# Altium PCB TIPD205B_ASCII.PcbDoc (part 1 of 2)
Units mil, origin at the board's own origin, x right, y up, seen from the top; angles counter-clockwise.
Board outline 684.25 x 4724.41 mil, 4 copper layers (Top Layer, Signal Layer 1, Signal Layer 2, Bottom Layer), stack 61.6 mil thick; 36 components, 24 nets, 156 pads, 59 vias.
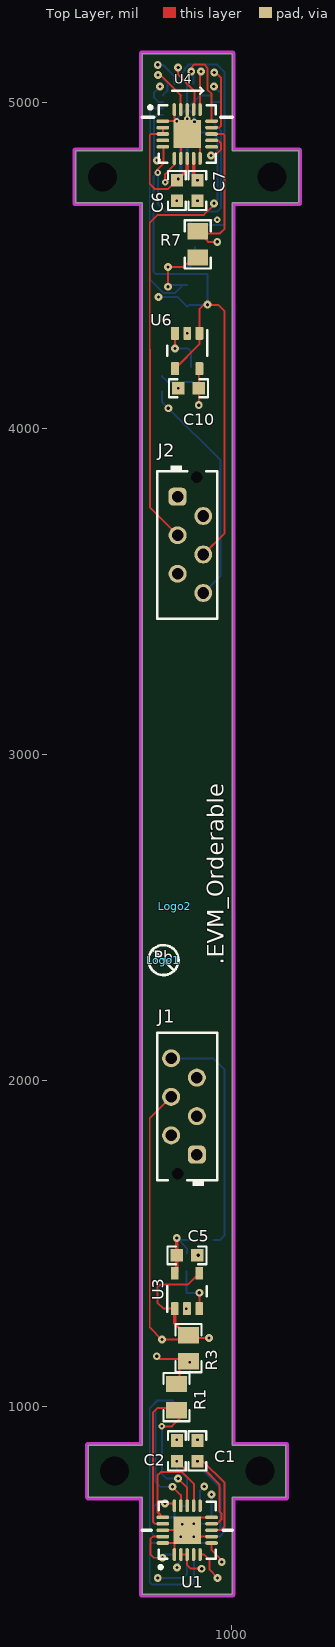
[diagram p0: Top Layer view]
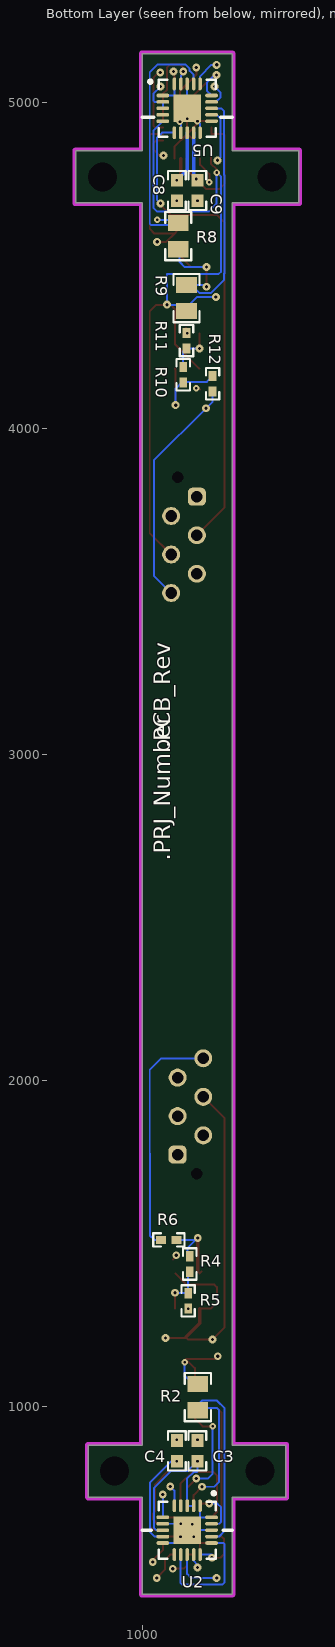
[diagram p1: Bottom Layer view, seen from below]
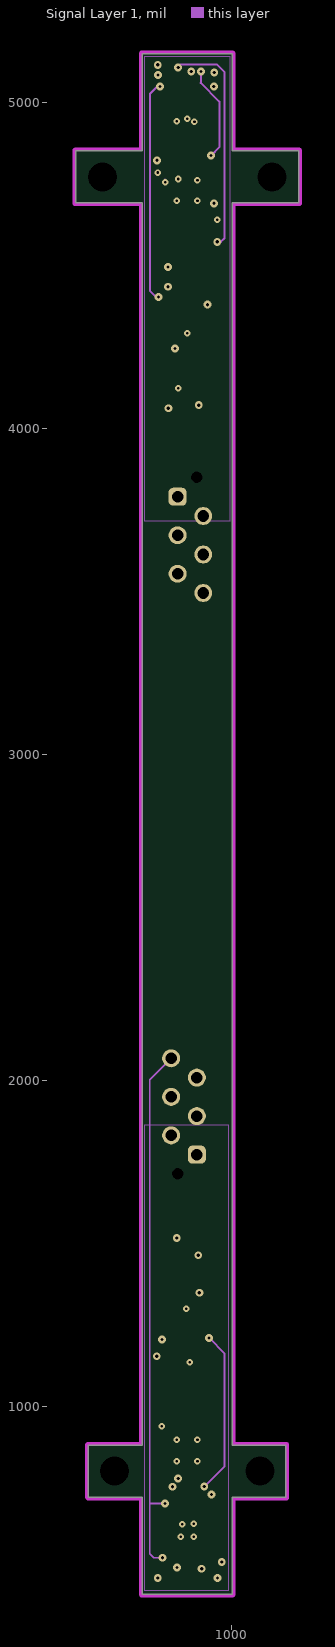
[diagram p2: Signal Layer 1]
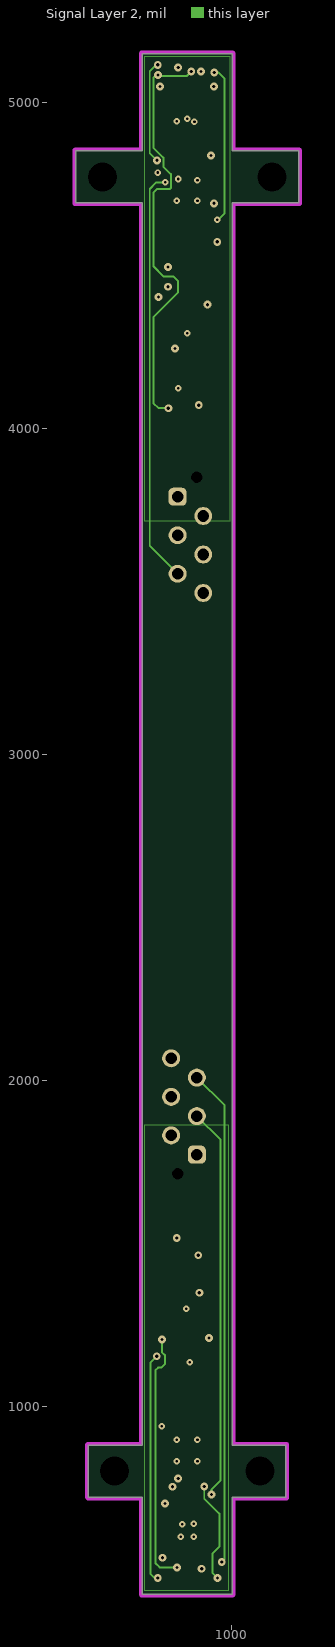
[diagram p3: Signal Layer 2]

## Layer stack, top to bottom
Top Solder: solder mask 0.4, Solder Resist, Dk 3.5
Top Layer: signal copper 1.4
Dielectric 1: prepreg 8, FR-4, Dk 4.2
Signal Layer 1: signal copper 1.4
Dielectric 2: core 40, FR-4, Dk 4.2
Signal Layer 2: signal copper 1.4
Dielectric 3: prepreg 8, FR-4, Dk 4.2
Bottom Layer: signal copper 1.4
Bottom Solder: solder mask 0.4, Solder Resist, Dk 3.5

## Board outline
725,425 725,723.03 560.04,723.03 560.04,882.87 725,882.87 725,4691.54 520.67,4691.54 520.67,4851.38 725,4851.38 725,5149.41 1000.59,5149.41 1000.59,4851.38 1204.92,4851.38 1204.92,4691.54 1000.59,4691.54 1000.59,882.87 1165.55,882.87 1165.55,723.03 1000.59,723.03 1000.59,425

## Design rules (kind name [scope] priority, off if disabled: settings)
AcuteAngle [All] p0: scope1count=1 scope1_0_kind=Board scope1_0_value=Board scope2count=1 scope2_0_kind=Board scope2_0_value=Board commentlength=0 minimum=4.50000000000000E+0001
AcuteAngle [All] p1: minimum=4.50000000000000E+0001 checktracksonly=FALSE
AssemblyTestPointUsage [All] p0: scope1count=1 scope1_0_kind=Board scope1_0_value=Board scope2count=1 scope2_0_kind=Board scope2_0_value=Board commentlength=0
AssemblyTestPointUsage [All] p1: valid=2
AssemblyTestpoint [All] p0: scope1count=1 scope1_0_kind=Board scope1_0_value=Board scope2count=1 scope2_0_kind=Board scope2_0_value=Board commentlength=0
Clearance [All] p0: scope1count=1 scope1_0_kind=Board scope1_0_value=Board scope2count=1 scope2_0_kind=Board scope2_0_value=Board commentlength=0 gap=4.9
Clearance Clearance_Poly [All] p0 off: scope1count=1 scope1_0_kind=Board scope1_0_value=Board scope2count=1 scope2_0_kind=Board scope2_0_value=Board commentlength=48 gap=8 // Protel DXP Scope 1 Expression Was: InPolygon
Clearance Clearance_BoardEdge [All] p0 off: scope1count=1 scope1_0_kind=Board scope1_0_value=Board scope2count=1 scope2_0_kind=Board scope2_0_value=Board commentlength=48 gap=20 // Protel DXP Scope 2 Expression Was: IsKeepOut
Clearance Clearance_BoardEdge_Poly [All] p0 off: scope1count=1 scope1_0_kind=Board scope1_0_value=Board scope2count=1 scope2_0_kind=Board scope2_0_value=Board commentlength=48 gap=25 // Protel DXP Scope 2 Expression Was: IsKeepOut
Clearance Clearance_BoardEdge_MountingHoles [All] p0 off: scope1count=1 scope1_0_kind=Board scope1_0_value=Board scope2count=1 scope2_0_kind=Board scope2_0_value=Board commentlength=48 gap=40 // Protel DXP Scope 2 Expression Was: IsKeepOut
Clearance Clearance_Keepouts [All] p0 off: scope1count=1 scope1_0_kind=Board scope1_0_value=Board scope2count=1 scope2_0_kind=Board scope2_0_value=Board commentlength=99 gap=0 // Protel DXP Scope 2 Expression Was: ((IsTrack Or IsArc) And Not InPoly) And IsFree and IsKeepOut
Clearance Clearance_Keepouts [((IsTrack Or IsArc) And Not InPoly) And IsFree and IsKeepOut vs ((IsTrack Or IsArc) And Not InPoly) And IsFree and IsKeepOut] p1: gap=0
Clearance Clearance_BoardEdge_MountingHoles [OnCopper and InComponentClass('Mounting Holes') vs IsKeepOut] p2: gap=40
Clearance Clearance_BoardEdge_Poly [OnCopper and InPoly vs IsKeepOut] p3: gap=25
Clearance Clearance_BoardEdge [OnCopper and Not InComponentClass('Logo') and not InComponentClass('FiducialMark') and not InRegion(1000,500,4000,800) and Not IsKeepout vs IsKeepOut] p4: gap=20
Clearance Clearance_Poly [InPolygon] p5: gap=8
Clearance [All] p6: gap=4.9
ComponentClearance [All] p0 off: scope1count=1 scope1_0_kind=Board scope1_0_value=Board scope2count=1 scope2_0_kind=Board scope2_0_value=Board commentlength=105 gap=7 collisioncheckmode=3 // Protel DXP Scope 2 Expression Was: Not InComponentClass('Hardware') And  Not InComponentClass('Logo')
ComponentClearance ComponentClearance_THtoTH [All] p0 off: scope1count=1 scope1_0_kind=Board scope1_0_value=Board scope2count=1 scope2_0_kind=Board scope2_0_value=Board commentlength=54 gap=10 collisioncheckmode=3 // Protel DXP Scope 2 Expression Was: IsThruComponent
ComponentClearance ComponentClearance_THtoSMT [All] p0 off: scope1count=1 scope1_0_kind=Board scope1_0_value=Board scope2count=1 scope2_0_kind=Board scope2_0_value=Board commentlength=91 gap=10 collisioncheckmode=3 // Protel DXP Scope 2 Expression Was: IsSMTComponent And  Not InComponentClass('Hardware')
ComponentClearance ComponentClearance_SmallPassives [All] p0 off: scope1count=1 scope1_0_kind=Board scope1_0_value=Board scope2count=1 scope2_0_kind=Board scope2_0_value=Board commentlength=508 gap=20 collisioncheckmode=3 // Protel DXP Scope 2 Expression Was: HasFootprint('0201*') or HasFootprint('0402*') or HasFootprint('0508') or HasFootprint('0603*') or HasFootprint('0612') or HasFootprint('0805*') or HasFootprint('0815*') or HasFootprint('0830*') or HasFootprint('1206*') or HasFootprint('1210*') or HasFootprint('1808*') or HasFootprint('1812*') or HasFootprint('1825*') or HasFootprint('2010*') or HasFootprint('2220*') or HasFootprint('2225*') or HasFootprint('2512*') or HasFootprint('2728*') or HasFootprint('3518*')
ComponentClearance ComponentClearance_MountingHoles [All] p0 off: scope1count=1 scope1_0_kind=ComponentClass scope1_0_value="Mounting Holes" scope2count=1 scope2_0_kind=Board scope2_0_value=Board commentlength=90 gap=10 collisioncheckmode=3 // Protel DXP Scope 2 Expression Was: InAnyComponent And Not InComponentClass('Hardware')
ComponentClearance ComponentClearance_ScrewToNut [All] p0 off: scope1count=1 scope1_0_kind=Board scope1_0_value=Board scope2count=1 scope2_0_kind=Board scope2_0_value=Board commentlength=71 gap=5 collisioncheckmode=3 // Protel DXP Scope 2 Expression Was: (HasFootprint('Keystone_1902C'))
ComponentClearance ComponentClearance_Logo [All] p0: scope1count=1 scope1_0_kind=ComponentClass scope1_0_value=Logo scope2count=1 scope2_0_kind=Board scope2_0_value=Board commentlength=0 gap=0 collisioncheckmode=3
ComponentClearance ComponentClearance_Shunt [All] p0: scope1count=1 scope1_0_kind=ComponentClass scope1_0_value=Header scope2count=1 scope2_0_kind=ComponentClass scope2_0_value=Shunt commentlength=0 gap=0 collisioncheckmode=3
ComponentClearance ComponentClearance_MountingHoles_FiducialMarks [All] p0: scope1count=1 scope1_0_kind=ComponentClass scope1_0_value="Mounting Holes" scope2count=1 scope2_0_kind=ComponentClass scope2_0_value=FiducialMark commentlength=0 gap=7 collisioncheckmode=3
ComponentClearance ComponentClearance_MountingHoles_FiducialMarks [InComponentClass('Mounting Holes') vs InComponentClass('FiducialMark')] p1: gap=7 collisioncheckmode=3 verticalgap=10 showdistances=FALSE
ComponentClearance ComponentClearance_Shunt [InComponentClass('Header') vs InComponentClass('Shunt')] p2: gap=0 collisioncheckmode=3 verticalgap=0 showdistances=FALSE
ComponentClearance ComponentClearance_Logo [InComponentClass('Logo')] p3: gap=0 collisioncheckmode=3 verticalgap=0 showdistances=FALSE
ComponentClearance ComponentClearance_ScrewToNut [(HasFootprint('NY PMS 440 0025 PH')) vs (HasFootprint('Keystone_1902C'))] p4: gap=5 collisioncheckmode=3 verticalgap=10 showdistances=FALSE
ComponentClearance ComponentClearance_MountingHoles [InComponentClass('Mounting Holes') vs InAnyComponent And Not InComponentClass('Hardware')] p5: gap=10 collisioncheckmode=3 verticalgap=10 showdistances=TRUE
ComponentClearance ComponentClearance_SmallPassives [HasFootprint('0201*') or HasFootprint('0402*') or HasFootprint('0508') or HasFootprint('0603*') or HasFootprint('0612') or HasFootprint('0805*') or HasFootprint('0815*') or HasFootprint('0830*') or HasFootprint('1206*') or HasFootprint('1210*') or HasFootprint('1808*') or HasFootprint('1812*') or HasFootprint('1825*') or HasFootprint('2010*') or HasFootprint('2220*') or HasFootprint('2225*') or HasFootprint('2512*') or HasFootprint('2728*') or HasFootprint('3518*') vs HasFootprint('0201*') or HasFootprint('0402*') or HasFootprint('0508') or HasFootprint('0603*') or HasFootprint('0612') or HasFootprint('0805*') or HasFootprint('0815*') or HasFootprint('0830*') or HasFootprint('1206*') or HasFootprint('1210*') or HasFootprint('1808*') or HasFootprint('1812*') or HasFootprint('1825*') or HasFootprint('2010*') or HasFootprint('2220*') or HasFootprint('2225*') or HasFootprint('2512*') or HasFootprint('2728*') or HasFootprint('3518*')] p6: gap=20 collisioncheckmode=3 verticalgap=10 showdistances=FALSE
ComponentClearance ComponentClearance_THtoSMT [IsThruComponent And  Not InComponentClass('Hardware') vs IsSMTComponent And  Not InComponentClass('Hardware')] p7: gap=10 collisioncheckmode=3 verticalgap=10 showdistances=FALSE
ComponentClearance ComponentClearance_THtoTH [IsThruComponent vs IsThruComponent] p8: gap=10 collisioncheckmode=3 verticalgap=10 showdistances=FALSE
ComponentClearance [Not InComponentClass('Hardware') And  Not InComponentClass('Logo') vs Not InComponentClass('Hardware') And  Not InComponentClass('Logo')] p9: gap=7 collisioncheckmode=3 verticalgap=7 showdistances=TRUE
DiffPairsRouting [All] p0: scope1count=1 scope1_0_kind=Board scope1_0_value=Board scope2count=1 scope2_0_kind=Board scope2_0_value=Board commentlength=0
DiffPairsRouting [All] p1: maxlimit=100 minlimit=10 mostfreqgap=10 toplayer_minwidth=15 toplayer_maxwidth=15 toplayer_prefwidth=15 midlayer1_minwidth=15 midlayer1_maxwidth=15 midlayer1_prefwidth=15 midlayer2_minwidth=15 midlayer2_maxwidth=15 midlayer2_prefwidth=15 bottomlayer_minwidth=15 bottomlayer_maxwidth=15 bottomlayer_prefwidth=15 maxuncoupledlength=1000
FabricationTestPointUsage TestPointUsage [All] p0: scope1count=1 scope1_0_kind=Board scope1_0_value=Board scope2count=1 scope2_0_kind=Board scope2_0_value=Board commentlength=0 valid=2 allowmultiple=FALSE
FabricationTestPointUsage TestPointUsage [All] p1: valid=2 allowmultiple=FALSE
FabricationTestpoint Testpoint [All] p0: scope1count=1 scope1_0_kind=Board scope1_0_value=Board scope2count=1 scope2_0_kind=Board scope2_0_value=Board commentlength=0 side=3 testpointundercomponent=TRUE minsize=40 maxsize=100 preferedsize=60 minholesize=0 maxholesize=40 preferedholesize=32 testpointgrid=1
FabricationTestpoint Testpoint [All] p1: side=3 testpointundercomponent=TRUE minsize=40 maxsize=100 preferedsize=60 minholesize=0 maxholesize=40 preferedholesize=32 testpointgrid=1 allowsidetop=TRUE allowsidebottom=TRUE usegrid=TRUE gridtolerance=0.01
FanoutControl Fanout_Small [All] p0 off: scope1count=1 scope1_0_kind=Board scope1_0_value=Board scope2count=1 scope2_0_kind=Board scope2_0_value=Board commentlength=84 // Protel DXP Scope 1 Expression Was: (CompPinCount < 5)   Fanout_Small (Default Rule)
FanoutControl Fanout_Default [All] p0: scope1count=1 scope1_0_kind=Board scope1_0_value=Board scope2count=1 scope2_0_kind=Board scope2_0_value=Board commentlength=30 // Fanout_Default (Default Rule)
FanoutControl Fanout_SOIC [All] p0 off: scope1count=1 scope1_0_kind=Board scope1_0_value=Board scope2count=1 scope2_0_kind=Board scope2_0_value=Board commentlength=71 // Protel DXP Scope 1 Expression Was: IsSOIC   Fanout_SOIC (Default Rule)
FanoutControl Fanout_BGA [All] p0 off: scope1count=1 scope1_0_kind=Board scope1_0_value=Board scope2count=1 scope2_0_kind=Board scope2_0_value=Board commentlength=69 // Protel DXP Scope 1 Expression Was: IsBGA   Fanout_BGA (Default Rule)
FanoutControl Fanout_LCC [All] p0 off: scope1count=1 scope1_0_kind=Board scope1_0_value=Board scope2count=1 scope2_0_kind=Board scope2_0_value=Board commentlength=69 // Protel DXP Scope 1 Expression Was: IsLCC   Fanout_LCC (Default Rule)
FanoutControl Fanout_LCC [IsLCC] p1: bgadir=Out bgaviamode=Centered fanoutstyle=Auto fanoutdirection=Alternating viagrid=1 // Fanout_LCC (Default Rule)
FanoutControl Fanout_BGA [IsBGA] p2: bgadir=Out bgaviamode=Centered fanoutstyle=Auto fanoutdirection=Alternating viagrid=1 // Fanout_BGA (Default Rule)
FanoutControl Fanout_Default [All] p4: bgadir=Out bgaviamode=Centered fanoutstyle=Auto fanoutdirection=Alternating viagrid=1 // Fanout_Default (Default Rule)
FanoutControl Fanout_Small [(CompPinCount < 5)] p5: bgadir=Out bgaviamode=Centered fanoutstyle=Auto fanoutdirection=OutThenIn viagrid=1 // Fanout_Small (Default Rule)
Height [All] p0 off: scope1count=1 scope1_0_kind=Board scope1_0_value=Board scope2count=1 scope2_0_kind=Board scope2_0_value=Board commentlength=0
Height [All] p1 off: minheight=0 maxheight=1000 prefheight=500
HoleSize [All] p0: scope1count=1 scope1_0_kind=Board scope1_0_value=Board scope2count=1 scope2_0_kind=Board scope2_0_value=Board commentlength=0 absolutevalues=TRUE maxlimit=251 minlimit=8 maxpercent=80.000 minpercent=20.000
HoleSize [All] p1: absolutevalues=TRUE maxlimit=251 minlimit=8 maxpercent=80.000 minpercent=20.000
HoleToHoleClearance [All] p0: scope1count=1 scope1_0_kind=Board scope1_0_value=Board scope2count=1 scope2_0_kind=Board scope2_0_value=Board commentlength=0
LayerPairs [All] p0: scope1count=1 scope1_0_kind=Board scope1_0_value=Board scope2count=1 scope2_0_kind=Board scope2_0_value=Board commentlength=0 enforce=TRUE
MinimumAnnularRing [All] p0: scope1count=1 scope1_0_kind=Board scope1_0_value=Board scope2count=1 scope2_0_kind=Board scope2_0_value=Board commentlength=0 minimumring=6
MinimumAnnularRing MinimumAnnularRing_ThermalPadVias [All] p0 off: scope1count=1 scope1_0_kind=Board scope1_0_value=Board scope2count=1 scope2_0_kind=Board scope2_0_value=Board commentlength=63 minimumring=5.91 // Protel DXP Scope 1 Expression Was: IsVia and InAnyComponent
MinimumAnnularRing MinimumAnnularRing_ThermalPadVias [IsVia and InAnyComponent] p1: minimumring=5.91
MinimumAnnularRing [All] p2: minimumring=6
MinimumSolderMaskSliver [All] p0: scope1count=1 scope1_0_kind=Board scope1_0_value=Board scope2count=1 scope2_0_kind=Board scope2_0_value=Board commentlength=0
MinimumSolderMaskSliver MinimumSolderMaskSliver_Logo [All] p0: scope1count=1 scope1_0_kind=ComponentClass scope1_0_value=Logo scope2count=1 scope2_0_kind=ComponentClass scope2_0_value=Logo commentlength=0
MinimumSolderMaskSliver MinimumSolderMaskSliver_Logo [InComponentClass('Logo') vs InComponentClass('Logo')] p1: minsoldermaskwidth=0.7
MinimumSolderMaskSliver [All] p2: minsoldermaskwidth=3.1
NetAntennae [All] p0: scope1count=1 scope1_0_kind=Board scope1_0_value=Board scope2count=1 scope2_0_kind=Board scope2_0_value=Board commentlength=0
PasteMaskExpansion [All] p0: scope1count=1 scope1_0_kind=Board scope1_0_value=Board scope2count=1 scope2_0_kind=Board scope2_0_value=Board commentlength=0 expansion=0
PlaneClearance [All] p0: scope1count=1 scope1_0_kind=Board scope1_0_value=Board scope2count=1 scope2_0_kind=Board scope2_0_value=Board commentlength=0 clearance=20
PlaneConnect [All] p0: scope1count=1 scope1_0_kind=Board scope1_0_value=Board scope2count=1 scope2_0_kind=Board scope2_0_value=Board commentlength=0 planeconnectstyle=Relief reliefexpansion=10 reliefentries=4 reliefconductorwidth=10 reliefairgap=10
PlaneConnect [All] p1: planeconnectstyle=Relief reliefexpansion=10 reliefentries=4 reliefconductorwidth=10 reliefairgap=10
PolygonConnect [All] p0: scope1count=1 scope1_0_kind=Board scope1_0_value=Board scope2count=1 scope2_0_kind=Board scope2_0_value=Board commentlength=0 connectstyle=Direct reliefconductorwidth=10 reliefentries=4 polygonreliefangle="90 Angle"
PolygonConnect [All] p1: connectstyle=Direct reliefconductorwidth=10 reliefentries=4 polygonreliefangle="90 Angle" airgapwidth=10
RoutingCorners [All] p0: scope1count=1 scope1_0_kind=Board scope1_0_value=Board scope2count=1 scope2_0_kind=Board scope2_0_value=Board commentlength=0 cornerstyle=45-Degree minsetback=100 maxsetback=100
RoutingLayers [All] p0: scope1count=1 scope1_0_kind=Board scope1_0_value=Board scope2count=1 scope2_0_kind=Board scope2_0_value=Board commentlength=0 top layer=Automatic mid layer 1=Automatic mid layer 2=Automatic bottom layer=Automatic
RoutingPriority [All] p0: scope1count=1 scope1_0_kind=Board scope1_0_value=Board scope2count=1 scope2_0_kind=Board scope2_0_value=Board commentlength=0
RoutingTopology [All] p0: scope1count=1 scope1_0_kind=Board scope1_0_value=Board scope2count=1 scope2_0_kind=Board scope2_0_value=Board commentlength=0 topology=Shortest
RoutingVias [All] p0: scope1count=1 scope1_0_kind=Board scope1_0_value=Board scope2count=1 scope2_0_kind=Board scope2_0_value=Board commentlength=0 holewidth=10 width=24 viastyle="Through Hole" minholewidth=8 minwidth=20 maxholewidth=999 maxwidth=999
RoutingVias ThermalPadVias [All] p0 off: scope1count=1 scope1_0_kind=Board scope1_0_value=Board scope2count=1 scope2_0_kind=Board scope2_0_value=Board commentlength=63 holewidth=8 width=19.68 viastyle="Through Hole" minholewidth=7.87 minwidth=19.68 maxholewidth=999 maxwidth=999 // Protel DXP Scope 1 Expression Was: IsVia and InAnyComponent
RoutingVias ThermalPadVias [IsVia and InAnyComponent] p1: holewidth=8 width=19.68 viastyle="Through Hole" minholewidth=7.87 minwidth=19.68 maxholewidth=999 maxwidth=999
RoutingVias [All] p2: holewidth=10 width=24 viastyle="Through Hole" minholewidth=8 minwidth=20 maxholewidth=999 maxwidth=999
ShortCircuit [All] p0: scope1count=1 scope1_0_kind=Board scope1_0_value=Board scope2count=1 scope2_0_kind=Board scope2_0_value=Board commentlength=0 allowed=FALSE
SilkToBoardRegionClearance [All] p0: scope1count=1 scope1_0_kind=Board scope1_0_value=Board scope2count=1 scope2_0_kind=Board scope2_0_value=Board commentlength=0
SilkToSilkClearance [All] p0 off: scope1count=1 scope1_0_kind=Board scope1_0_value=Board scope2count=1 scope2_0_kind=Board scope2_0_value=Board commentlength=0
SilkToSilkClearance SilkToSilkClearance_Pb-FreeLogo [All] p0 off: scope1count=1 scope1_0_kind=Board scope1_0_value=Board scope2count=1 scope2_0_kind=Board scope2_0_value=Board commentlength=120 // Protel DXP Scope 2 Expression Was: (HasFootprint('Pb-Free_Overlay_Medium') OR HasFootprint('Pb-Free_Overlay_Small'))
SilkToSilkClearance SilkToSilkClearance_Pb-FreeLogo [(HasFootprint('Pb-Free_Overlay_Medium') OR HasFootprint('Pb-Free_Overlay_Small')) vs (HasFootprint('Pb-Free_Overlay_Medium') OR HasFootprint('Pb-Free_Overlay_Small'))] p1 off: silktosilkclearance=0
SilkToSilkClearance [All] p2 off: silktosilkclearance=3
SilkToSolderMaskClearance "Silk to Solder Mask Opening" [All] p0 off: scope1count=1 scope1_0_kind=Board scope1_0_value=Board scope2count=1 scope2_0_kind=Board scope2_0_value=Board commentlength=71 // Protel DXP Scope 2 Expression Was: Not InComponentClass('Hardware')
SilkToSolderMaskClearance SilkToComonentPadClearance [All] p0 off: scope1count=1 scope1_0_kind=Board scope1_0_value=Board scope2count=1 scope2_0_kind=Board scope2_0_value=Board commentlength=71 // Protel DXP Scope 2 Expression Was: Not InComponentClass('Hardware')
SilkToSolderMaskClearance SilkToComonentPadClearance [IsPad and InAnycomponent vs Not InComponentClass('Hardware')] p1: minsilkscreentomaskgap=3 clearancetoexposedcopper=TRUE
SilkToSolderMaskClearance "Silk to Solder Mask Opening" [Not InComponentClass('Hardware') vs Not InComponentClass('Hardware')] p2: minsilkscreentomaskgap=3 clearancetoexposedcopper=FALSE
SolderMaskExpansion [All] p0: scope1count=1 scope1_0_kind=Board scope1_0_value=Board scope2count=1 scope2_0_kind=Board scope2_0_value=Board commentlength=0 expansion=0
SolderMaskExpansion [All] p1: expansion=0
UnRoutedNet [All] p0: scope1count=1 scope1_0_kind=Board scope1_0_value=Board scope2count=1 scope2_0_kind=Board scope2_0_value=Board commentlength=0
UnpouredPolygon [All] p0: scope1count=1 scope1_0_kind=Board scope1_0_value=Board scope2count=1 scope2_0_kind=Board scope2_0_value=Board commentlength=0
Width [All] p0: scope1count=1 scope1_0_kind=Board scope1_0_value=Board scope2count=1 scope2_0_kind=Board scope2_0_value=Board commentlength=0 maxlimit=100 minlimit=6 preferedwidth=6
Width [All] p1: maxlimit=100 minlimit=6 preferedwidth=6 minimp=50.000000 maximp=50.000000 favimp=50.000000 checkconnectedcopper=TRUE
15 further rules are at their usual default settings.

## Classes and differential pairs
component class AssemblyNote: ZZ2 ZZ3 ZZ4
component class TIPD205BHW: Logo1 Logo2 Logo3 Logo? ZZ2 ZZ3 ZZ4
component class Logo: Logo2

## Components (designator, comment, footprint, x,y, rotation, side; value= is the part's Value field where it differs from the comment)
C1 "C0603C105K3RACTU" 0603 894.29,864.92 r90 top
C2 "C0603C105K3RACTU" 0603 831.3,864.92 r270 top
C3 "C0603C105K3RACTU" 0603 831.3,864.92 r90 bottom
C4 "C0603C105K3RACTU" 0603 894.29,864.92 r270 bottom
C5 "C0603C105K3RACTU" 0603 862.05,1464.61 r0 top
C6 "C0603C105K3RACTU" 0603 831.3,4729.72 r270 top
C7 "C0603C105K3RACTU" 0603 894.29,4729.7 r90 top
C8 "C0603C105K3RACTU" 0603 894.29,4729.7 r270 bottom
C9 "C0603C105K3RACTU" 0603 831.3,4729.72 r90 bottom
C10 "C0603C105K3RACTU" 0603 866.73,4123.43 r180 top
J1 "292207-6" TE_292207-6 862.8,1921.06 r90 top
J2 "292207-6" TE_292207-6 862.8,3643.11 r270 top
Logo1 "Pb-Free Symbol" Pb-Free_Overlay_Small 790,2370 r0 top
Logo2 "Texas Instruments" TI_Symbol_Overlay_Small 825,2535 r0 top
Logo3 "FCC disclaimer" FCC_disclaimer -2112.55,3535 r180 bottom
R1 "RC0805FR-075R11L" 0805_HV 830,1030 r270 top
R2 "RC0805FR-075R11L" 0805_HV 830,1030 r90 bottom
R3 "RT0805BRD0749R9L" 0805_HV 866.73,1179.88 r270 top
R4 "CRCW040210K0FKED" 0402 855,1437.99 r90 bottom
R5 "CRCW040210K0FKED" 0402 860,1325 r90 bottom
R6 "CRCW040210K0FKED" 0402 919.25,1511.89 r180 bottom
R7 "RC0805FR-075R11L" 0805_HV 895,4564.39 r90 top
R8 "RC0805FR-075R11L" 0805_HV 890,4589.98 r270 bottom
R9 "RT0805BRD0749R9L" 0805_HV 865,4400 r90 bottom
R10 "CRCW040210K0FKED" 0402 875,4164.76 r270 bottom
R11 "CRCW040210K0FKED" 0402 865,4269.12 r270 bottom
R12 "CRCW040210K0FKED" 0402 785,4137.17 r90 bottom
U1 "DRV425RTJR" RTJ20_no_vias 862.8,621.85 r90 top
U2 "DRV425RTJR" RTJ20_no_vias 862.8,621.85 r270 bottom
U3 "OPA320AIDBVT" DBV0005A_N 862.05,1355.32 r90 top
U4 "DRV425RTJR" RTJ20_no_vias 862.8,4902.95 r0 top
U5 "DRV425RTJR" RTJ20_no_vias 862.8,4981.69 r180 bottom
U6 "OPA320AIDBVT" DBV0005A_N 862.8,4237.6 r270 top
ZZ2 "This Assembly Note will show in the PcbDoc and associated outputs" AssemblyNote 2730,4704.11 r0 top
ZZ3 "This Assembly Note will show in the PcbDoc and associated outputs" AssemblyNote 2730,4615.56 r0 top
ZZ4 "This Assembly Note will show in the PcbDoc and associated outputs" AssemblyNote 2730,4527 r0 top

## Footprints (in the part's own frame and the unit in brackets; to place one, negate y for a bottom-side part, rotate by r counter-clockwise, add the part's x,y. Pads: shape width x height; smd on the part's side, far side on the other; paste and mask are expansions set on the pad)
0402 [mm] "0402 from SM-752 data"
  rect 0.8x0.6 smd: 1(-0.6,0) 2(0.6,0)
  silkscreen extent -1.22,-0.52 1.22,0.52
0603 [mm] "0603 from SM-752 data"
  rect 1x0.95 smd: 1(-0.8,0) 2(0.8,0)
  silkscreen extent -1.52,-0.69 1.52,0.69
0805_HV [mil] "0805 with 30mil clearance between pads"
  rect 50x63 smd: 1(-40,0) 2(40,0)
  silkscreen extent -74,-40 74,40
AssemblyNote [mil] "Assembly Note"
DBV0005A_N [mm] "SOT23, 5-Leads, Body 2.9x1.6mm, Pitch 0.95mm, Lead Span 2.8mm, IPC Medium Density"
  rrect17% 1x0.6 smd: 1(-1.375,0.95) 2(-1.375,0) 3(-1.375,-0.95) 4(1.375,-0.95) 5(1.375,0.95)
  silkscreen extent -1.63,-1.55 0.38,1.55
FCC_disclaimer [mil]
Pb-Free_Overlay_Small [mil]
  silkscreen extent -46,-46 46,46
RTJ20_no_vias [mm]
  oval 1x0.28 smd paste-0.025 mask+0: 1(-1.9,1) 2(-1.9,0.5) 3(-1.9,0) 4(-1.9,-0.5) 5(-1.9,-1) 11(1.9,-1) 12(1.9,-0.5) 13(1.9,0) 14(1.9,0.5) 15(1.9,1)
  oval 0.28x1 smd paste-0.025 mask+0: 6(-1,-1.9) 7(-0.5,-1.9) 8(0,-1.9) 9(0.5,-1.9) 10(1,-1.9) 16(1,1.9) 17(0.5,1.9) 18(0,1.9) 19(-0.5,1.9) 20(-1,1.9)
  rect 2.15x2.15 smd paste-1.075 mask+0: 21(0,0)
  silkscreen extent -3,-2.23 2.23,2.22
TE_292207-6 [mm] "Header(shrouded), 1.5mm, 6x1, TH"
  rrect50% 1.4x1.4 hole 0.9: 1(-3.75,-0.75)
  round 1.4 hole 0.9: 2(-2.25,1.25) 3(-0.75,-0.75) 4(0.75,1.25) 5(2.25,-0.75) 6(3.75,1.25)
  round 0 hole 0.9 unplated: MH(-5.25,0.75)
  silkscreen extent -6.2,-2.35 5.75,2.35
TI_Symbol_Overlay_Small [mil]

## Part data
C1 C2 C3 C4 C5 C6 C7 C8 C9 C10: "CAP, CERM, 1 µF, 25 V, +/- 10%, X7R, 0603"
J1 J2: "Header(shrouded), 1.5mm, 6x1, Tin, TH"
Logo1: library part Pb-Free
Logo2: library part TI_Logo, "Texas Instrument Corporate Signature"
Logo3: library part FCC_disclaimer, "FCC_disclaimer"
R1 R2 R7 R8: "RES, 5.11, 1%, 0.125 W, 0805"
R3 R9: "RES, 49.9, 0.1%, 0.125 W, 0805"
R4 R5 R6 R10 R11 R12: "RES, 10.0 k, 1%, 0.063 W, 0402"
U1 U2 U4 U5: "Fully Integrated Precision Fluxgate Magnetic Field Sensor and readout, RTJ0020G (WQFN-20)"
U3 U6: "Precision, 20 MHz, 0.9 pA Ib, RRIO, CMOS Operational Amplifier, 1.8 to 5.5 V, -40 to 125 degC, 5-pin SOT23 (DBV0005A), Green (RoHS & no Sb/Br)"
ZZ2 ZZ3 ZZ4: library part AssemblyNote

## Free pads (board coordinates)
  round 0 hole 88.98 unplated: 5(602.56,4771.46) 5(639.17,802.95) 5(1086.42,802.95) 5(1123.03,4771.46)

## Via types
v1: diameter 24, hole 10, Top Layer to Bottom Layer, 24 vias
v2: diameter 20, hole 8, Top Layer to Bottom Layer, 19 vias
v3: diameter 24, hole 10, Top Layer to Bottom Layer, tented both sides, 12 vias
v4: diameter 20, hole 8, Top Layer to Bottom Layer, tented both sides, 4 vias

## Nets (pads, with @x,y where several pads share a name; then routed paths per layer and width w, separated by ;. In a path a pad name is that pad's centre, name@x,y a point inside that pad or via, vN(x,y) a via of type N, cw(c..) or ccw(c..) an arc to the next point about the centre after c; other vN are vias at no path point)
GND_H: C6.2 C7.1 C8.2 C9.1 C10.2 J2.2 R11.1 U4.1 U4.7 U4.10 U4.18 U4.20 U4.21 U5.1 U5.7 U5.10 U5.18 U5.20 U5.21 U6.2 | length 784.7
  Top Layer w6: U4.1@787.99,4942.32 823.43,4942.32 U4.20@823.43,4977.76 ; C10.2@823.7,4119.76 C10.2@835.24,4131.3 ; U4.21@827.36,4938.39 U4.21@862.8,4902.95 ; U4.7@843.11,4828.15 843.11,4883.27 U4.21@862.8,4902.95 ; U4.21@862.8,4915 U4.18@862.8,4989.8 ; U6.2@865,4286.84 866.73,4288.57 U6.2@866.73,4308.46 ; U4.10@902.17,4828.15 902.17,4863.58 U4.21@862.8,4902.95
  Bottom Layer w6: U5.10@823.43,4906.89 823.43,4934.45 v4(831.3,4942.32) 831.3,4950.2 U5.21@862.8,4981.69 ; R11.1@862.22,4292.75 R11.1@862.8,4293.32 ; U5.18@862.8,5056.5 U5.21@862.8,4981.69 ; U5.7@882.48,4906.89 882.48,4962.01 U5.21@862.8,4981.69 ; U5.20@902.17,5056.5 U5.21@902.17,5021.06 ; U5.1@937.6,5021.06 U5.21@902.17,5021.06 ; U5.21@862.8,4981.69 U5.21@902.17,5021.06
  other v2: 835.24,4123.43 862.8,4291.73 831.3,4698.23 894.29,4698.21
  other v4: 885,4940 862.8,4950
GND_V: C1.2 C2.1 C3.2 C4.1 C5.2 J1.2 R5.1 U1.1 U1.7 U1.10 U1.18 U1.20 U1.21 U2.1 U2.7 U2.10 U2.18 U2.20 U2.21 U3.2 | length 518.7
  Top Layer w6: U1.18@787.99,621.85 U1.21@860.59,621.85 ; U1.20@788.94,582.48 824.37,582.48 U1.1@824.37,547.05 ; v2(860,1301.38) U3.2@860,1307.32 ; U3.2@862.05,1301.18 U3.2@862.05,1305.27 ; v2(883.42,602.17) U1.7@937.6,602.17 U1.7@938.54,602.17 ; C5.2@893.54,1464.61 C5.2@906.26,1451.89 ; U1.21@899.96,661.22 U1.10@937.6,661.22
  Bottom Layer w6: U2.18@787.99,621.85 U2.21@862.8,621.85 ; U2.20@787.99,661.22 823.43,661.22 U2.1@823.43,696.65 ; U2.21@854.08,613.13 U2.21@858.36,608.85 ; v2(860,1301.38) R5.1@860,1307.52 ; U2.21@872.46,631.51 U2.21@876.74,627.24 ; v2(882.48,641.54) U2.7@937.6,641.54 ; U2.21@902.17,582.48 U2.10@937.6,582.48
  other v1: 896.48,1464.61
  other v2: 843.11,601.14 847.05,640.51 831.3,899.35 894.29,899.37
NetJ1_6: J1.6 R6.1 U1.15 U1.19 U2.15 U2.19 | length 2688.7
  Top Layer w6: v3(787.24,537.24) 760.76,537.24 750,548 750,595 757.17,602.17 U1.19@787.99,602.17 ; v3(795,703.54) 816.54,703.54 U1.15@823.43,696.65
  Signal Layer 1 w6: v3(787.24,537.24) 760.76,537.24 748,550 748,705 ; v3(795,703.54) 749.46,703.54 748,705 ; J1.6@813.58,2068.7 748,2003.12 748,705
  Bottom Layer w6: v3(787.24,537.24) 787.24,547.05 U2.15@823.43,547.05 ; U2.19@787.99,641.54 764.96,641.54 758.85,647.64 758.85,692.39 770,703.54 v3(795,703.54) ; J1.6@813.58,2068.7 942.83,2068.7 977.59,2033.94 976.84,1525.27 963.46,1511.89 R6.1@942.87,1511.89
NetJ2_6: J2.6 R12.1 U4.15 U4.19 U5.15 U5.19 | length 2571.9
  Top Layer w6: v3@769.72,5087.27 769.72,5089.29 772.59,5092.17 843.11,5021.65 842.9,5021.43 842.9,4977.97 U4.19@843.11,4977.76 ; v3(875,5094.76) 875,5106.17 885,5116.17 914.38,5116.17 924.9,5105.65 924.9,5066.52 924.59,5066.21 924.59,5038.94 937.6,5025.92 U4.15@937.6,4942.32
  Signal Layer 2 w6: v3@770.28,5087.27 770,5087.56 769.72,5087.27 769.72,5086.71 758.9,5075.89 758.9,4861.41 789.9,4830.41 789.9,4803.15 812.9,4780.15 812.9,4737.47 809.19,4733.76 769.35,4733.76 758.9,4723.31 758.9,4498.27 791.22,4465.94 821.22,4465.94 834.25,4452.91 834.25,4416.42 759.21,4341.38 759.21,4077.95 775,4062.17 v1(805,4062.17) ; v3@772.59,5089.58 770,5086.99 776.65,5080.34 860.58,5080.34 v3(875,5094.76)
  Bottom Layer w6: v3@769.72,5091.88 769.72,5087.27 774.89,5087.27 802.17,5060 802.17,5035.28 U5.15@787.99,5021.06 ; R12.1@785,4113.54 785,4082.17 v1(805,4062.17) 965,3902.17 965,3548.46 J2.6@912.01,3495.47 ; v3@870,5094.76 882.48,5082.28 U5.19@882.48,5056.5
  other v3: 773.32,5083.67
NetR1_1: R1.1 R2.2 R3.2 U2.13 | length 1131.4
  Top Layer w6: v1(769.21,1155) 777.8,1146.42 866.73,1146.42 839.17,1118.86 R1.1@839.17,1063.74
  Signal Layer 2 w6: v1(769.21,1155) 750,1135.79 750,488.9 763.9,475 v1@770,475
  Bottom Layer w6: v1@770,475 850,475 862.8,487.8 U2.13@862.8,547.05 ; R2.2@839.17,1063.74 870.67,1095.24 v2@870.67,1129.72
  other v1: 772.5,475
  other v2: 870,1136.57
NetR1_2: R1.2 U1.13 U1.17 | length 850
  Top Layer w6: v2(785,940) 815.83,940 839.17,963.35 839.17,996.81 771.81,996.81 757.44,982.44 757.44,647.44 763.35,641.54 U1.17@787.99,641.54 U1.17@788.94,641.54 ; v1(835,780) 862.8,752.2 U1.13@862.8,696.65
  Bottom Layer w6: v2(785,940) 785,795 800,780 v1(835,780)
NetR2_1: R2.1 U1.14 U2.17 | length 959.2
  Top Layer w6: v1(817.55,755) 843.11,729.44 U1.14@843.11,696.65
  Bottom Layer w5.91: 748,714.77 748,619.48 765.31,602.17 U2.17@788.94,602.17
  Bottom Layer w6: 748,714.77 748,995.81 771.68,1019.49 816.5,1019.49 839.17,996.81 771.81,996.81 765,990 765,770.55 780.55,755 v1(817.55,755)
NetR4_1: R4.1 R5.2 U3.3 | length 155.4
  Top Layer w6: U3.3@899.45,1301.18 900,1301.73 v1(900,1350)
  Bottom Layer w6: R4.1@860,1414.37 R5.2@860,1348.62 898.62,1348.62 v1(900,1350)
NetR7_1: R7.1 R8.2 R9.2 U5.13 | length 1042.6
  Top Layer w6: v1(803.74,4434.45) v1(803.74,4495) 850.51,4495 R7.1@886.42,4530.91
  Bottom Layer w6: 749.51,4932.17 749.51,4777.53 748,4776.01 748,4476.59 749.51,4475.07 749.51,4456.58 791.1,4415 825,4415 R9.2@850.35,4440.35 ; 749.49,4932.2 749.49,4952.4 ; 749.51,4952.43 749.51,4973.21 758,4981.69 U5.13@787.99,4981.69 ; v1(803.74,4434.45) 809.65,4440.35 R9.2@850.35,4440.35 ; v1(803.74,4495) 870,4495 886.42,4511.42 R8.2@886.42,4556.52 ; R9.2@862.8,4440.35 R9.2@850.35,4440.35
NetR7_2: R7.2 U4.13 U4.17 | length 1323.3
  Top Layer w6: v1@835,5104.76 835,5084.76 884.9,5034.86 884.9,4980.18 U4.17@882.48,4977.76 ; R7.2@895,4604.39 R7.2@901.56,4597.83 ; U4.13@937.6,4902.95 973.65,4902.95 977.59,4899.02 977.59,4612.24 963.19,4597.83 R7.2@901.56,4597.83 ; v3(955,4572.24) 927.15,4572.24 R7.2@901.56,4597.83
  Signal Layer 1 w6: v1@835,5109.76 841.41,5116.17 953.83,5116.17 977.59,5092.41 977.59,4584.06 965.78,4572.24 v3(955,4572.24)
  other v1: 835,5107.17
NetR8_1: R8.1 U4.14 U5.17 | length 1565
  Top Layer w6: U4.14@937.6,4922.64 961.11,4922.64 966.38,4927.9 966.38,5074.96 945.47,5095.87 v1(945.47,5091.92)
  Signal Layer 2 w6: v1(945.47,5091.92) 957.91,5091.92 977.59,5072.24 977.59,4658.86 976.97,4658.86 v2@957.93,4639.82
  Bottom Layer w6: U5.17@843.11,5056.5 843.11,5084.73 855.1,5096.72 855.1,5103.01 868.27,5116.17 953.83,5116.17 977.59,5092.41 977.59,4627.99 973.05,4623.45 862.8,4623.45 879.17,4639.82 v2@957.93,4639.82
  other v2: 955,4639.82
NetR10_1: R10.1 R11.2 U6.3 | length 144.7
  Top Layer w6: v1(825,4245.5) U6.3@825.39,4291.73
  Bottom Layer w6: v1(825,4245.5) R11.2@862.22,4245.5 ; R11.2@865,4245.5 875,4235.5 R10.1@875,4188.39
NetU1_12: U1.12 U1.16 | length 333.4
  Top Layer w6: U1.16@787.99,661.22 771.68,677.54 771.68,790 781.68,800 847.01,800 883.43,763.58 U1.12@883.43,696.65
NetU2_12: U2.12 U2.16 | length 386.2
  Bottom Layer w6: U2.16@787.99,582.48 752.48,582.48 748,578 748,462 755.15,454.85 878.54,454.85 883.72,460.02 883.72,545.81 U2.12@882.48,547.05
